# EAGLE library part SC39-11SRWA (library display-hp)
SINGLE DIGIT NUMERIC DISPLAY 9.9mm (0.39INCH) Source: SC39-11SRWA.pdf
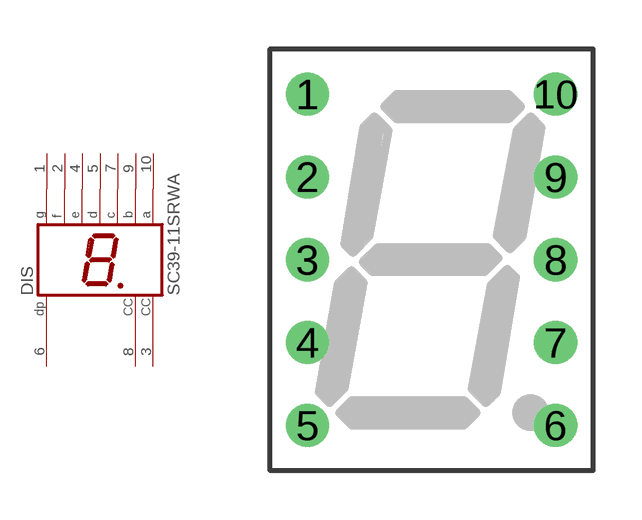
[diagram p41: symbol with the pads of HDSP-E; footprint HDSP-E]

Designator prefix DIS

## SC39-11SRWA (OC_FARNELL: unknown; OC_NEWARK: unknown)  [HDSP-E]
1  G  pas
2  F  pas
3  CC  pas
4  E  pas
5  D  pas
6  DP  pas
7  C  pas
8  CC  pas
9  B  pas
10  A  pas

## Footprint HDSP-E (pad centres in mm)
LED DISPLAY 10-mm 1 character 7 segment, decimal point right
drill 0.813 round: 1 -3.81,5.08; 2 -3.81,2.54; 3 -3.81,0; 4 -3.81,-2.54; 5 -3.81,-5.08; 6 3.81,-5.08; 7 3.81,-2.54; 8 3.81,0; 9 3.81,2.54; 10 3.81,5.08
